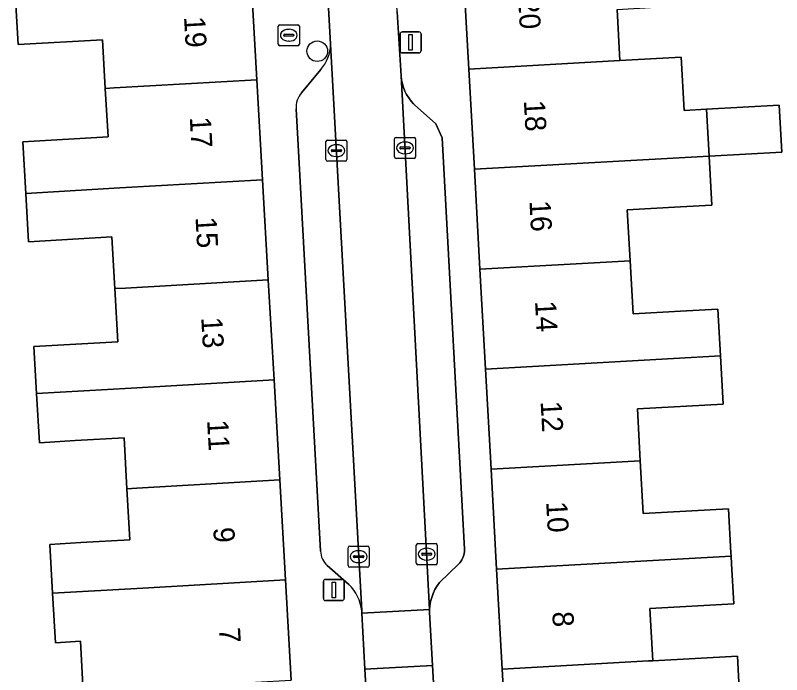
# Model space of a CAD drawing. Extents: x 160856 to 161310, y 384024 to 384878.
# Drawn here: x 161044.4 to 161080.75, y 384755.64 to 384786.93 of the extents above; entities that cross this region are included whole.
import ezdxf

# ---------------------------------------------------------------- set-up
doc = ezdxf.new("R2010")
doc.units = 0
for name, color, linetype in [('IMGEO_Boom', 7, 'Continuous'), ('IMGEO_Brandkraan', 7, 'Continuous'), ('IMGEO_Erf', 7, 'Continuous'), ('IMGEO_Kolk', 7, 'Continuous'), ('IMGEO_Lichtmast', 7, 'Continuous'), ('IMGEO_Pand', 7, 'Continuous'), ('IMGEO_Pand_nummerreeks', 7, 'Continuous'), ('IMGEO_Parkeervlak_open', 7, 'Continuous'), ('IMGEO_Rijbaan_lokaal_open', 7, 'Continuous'), ('IMGEO_Voetpad_open', 7, 'Continuous')]:
    doc.layers.add(name, color=color, linetype=linetype)

msp = doc.modelspace()

# ---------------------------------------------------------------- linework, layer by layer
at = {"layer": 'IMGEO_Boom'}
msp.add_circle((161058.723, 384785.224), 0.489, dxfattribs=at)
at = {"layer": 'IMGEO_Brandkraan'}
for p, q in [((161056.873, 384785.557), (161056.873, 384786.409)), ((161056.948, 384786.483), (161057.8, 384786.483)), ((161057.361, 384786.263), (161057.386, 384786.263)), ((161057.874, 384786.409), (161057.874, 384785.557)), ((161057.132, 384785.977), (161057.132, 384785.989)), ((161057.57, 384785.94), (161057.172, 384785.94)), ((161057.175, 384786.026), (161057.573, 384786.026)), ((161057.616, 384785.989), (161057.616, 384785.977)), ((161057.384, 384785.703), (161057.359, 384785.703)), ((161057.8, 384785.483), (161056.948, 384785.483))]:
    msp.add_line(p, q, dxfattribs=at)
for points in [[(161056.873, 384785.557), (161056.873, 384786.409)], [(161056.948, 384786.483), (161057.8, 384786.483)], [(161057.874, 384786.409), (161057.874, 384785.557)], [(161057.8, 384785.483), (161056.948, 384785.483)]]:
    msp.add_lwpolyline(points, dxfattribs=at)
for centre, radius, start, end in [((161056.95, 384786.407), 0.0765, 91.552, 178.448), ((161056.95, 384786.407), 0.0765, 91.552, 178.448), ((161057.798, 384786.407), 0.0765, 1.552, 88.448), ((161057.798, 384786.407), 0.0765, 1.552, 88.448), ((161057.172, 384785.986), 0.0403, 85.8775, 175.7526), ((161057.169, 384785.976), 0.0366, 178.938, 274.7102), ((161057.573, 384785.983), 0.043, 264.8664, 352.4533), ((161057.577, 384785.988), 0.0386, 1.7309, 96.639), ((161056.95, 384785.559), 0.0765, 181.552, 268.448), ((161056.95, 384785.559), 0.0765, 181.552, 268.448), ((161057.798, 384785.559), 0.0765, 271.552, 358.448), ((161057.798, 384785.559), 0.0765, 271.552, 358.448)]:
    msp.add_arc(centre, radius, start, end, dxfattribs=at)
for centre, major_axis, ratio, start_param, end_param in [((161057.36, 384785.983), (-0.387, 0.002), 0.722429, 4.712389, 7.853982), ((161057.385, 384785.983), (-0.39, 0.002), 0.717154, 1.570796, 4.712389)]:
    msp.add_ellipse(centre, major_axis=major_axis, ratio=ratio, start_param=start_param, end_param=end_param, dxfattribs=at)
at = {"layer": 'IMGEO_Erf'}
for points in [[(161047.627, 384754.817), (161047.489, 384757.224), (161046.302, 384757.156), (161046.168, 384759.498), (161046.035, 384761.818), (161047.517, 384761.903), (161049.834, 384762.036), (161049.695, 384764.464), (161049.558, 384766.875), (161047.24, 384766.743), (161045.541, 384766.646), (161045.408, 384768.982), (161045.281, 384771.204), (161049.263, 384771.434), (161049.117, 384773.958), (161049.102, 384774.223), (161048.976, 384776.411), (161045.027, 384776.185), (161044.896, 384778.48), (161044.756, 384780.929), (161048.801, 384781.161), (161048.67, 384783.459), (161048.538, 384785.766), (161044.542, 384785.537), (161044.402, 384787.978)], [(161072.949, 384787.211), (161073.083, 384784.777), (161075.991, 384784.939), (161076.132, 384782.412), (161077.185, 384782.47), (161080.631, 384782.66), (161080.753, 384780.441), (161077.309, 384780.251), (161077.438, 384777.926), (161075.957, 384777.843), (161073.43, 384777.701), (161073.566, 384775.283), (161073.707, 384772.761), (161076.232, 384772.901), (161077.732, 384772.984), (161077.856, 384770.761), (161077.983, 384768.478), (161073.91, 384768.252), (161074.047, 384765.789), (161074.186, 384763.289), (161078.225, 384763.513), (161078.345, 384761.413), (161078.353, 384761.267), (161078.374, 384760.898), (161078.482, 384758.995), (161074.501, 384758.773), (161074.639, 384756.3), (161078.652, 384756.524), (161078.791, 384754.027)]]:
    msp.add_lwpolyline(points, dxfattribs=at)
at = {"layer": 'IMGEO_Kolk'}
for p, q in [((161059.133, 384780.08), (161059.133, 384780.932)), ((161059.208, 384781.006), (161060.06, 384781.006)), ((161060.134, 384780.932), (161060.134, 384780.08)), ((161062.387, 384780.21), (161062.387, 384781.062)), ((161062.462, 384781.136), (161063.314, 384781.136)), ((161062.875, 384780.916), (161062.9, 384780.916)), ((161063.388, 384781.062), (161063.388, 384780.21)), ((161059.392, 384780.5), (161059.392, 384780.512)), ((161059.83, 384780.463), (161059.432, 384780.463)), ((161059.435, 384780.549), (161059.833, 384780.549)), ((161059.621, 384780.786), (161059.646, 384780.786)), ((161059.876, 384780.512), (161059.876, 384780.5)), ((161062.646, 384780.63), (161062.646, 384780.642)), ((161063.084, 384780.593), (161062.686, 384780.593)), ((161062.689, 384780.679), (161063.087, 384780.679)), ((161063.13, 384780.642), (161063.13, 384780.63)), ((161059.644, 384780.226), (161059.619, 384780.226)), ((161063.314, 384780.136), (161062.462, 384780.136)), ((161062.898, 384780.356), (161062.873, 384780.356)), ((161060.06, 384780.006), (161059.208, 384780.006)), ((161060.187, 384760.812), (161060.187, 384761.664)), ((161060.262, 384761.738), (161061.114, 384761.738)), ((161061.188, 384761.664), (161061.188, 384760.812)), ((161063.417, 384760.932), (161063.417, 384761.784)), ((161063.492, 384761.858), (161064.344, 384761.858)), ((161063.905, 384761.638), (161063.93, 384761.638)), ((161064.418, 384761.784), (161064.418, 384760.932)), ((161060.446, 384761.232), (161060.446, 384761.244)), ((161060.884, 384761.195), (161060.486, 384761.195)), ((161060.489, 384761.281), (161060.887, 384761.281)), ((161060.675, 384761.518), (161060.7, 384761.518)), ((161060.93, 384761.244), (161060.93, 384761.232)), ((161063.676, 384761.352), (161063.676, 384761.364)), ((161064.114, 384761.315), (161063.716, 384761.315)), ((161063.719, 384761.401), (161064.117, 384761.401)), ((161064.16, 384761.364), (161064.16, 384761.352)), ((161060.698, 384760.958), (161060.673, 384760.958)), ((161064.344, 384760.858), (161063.492, 384760.858)), ((161063.928, 384761.078), (161063.903, 384761.078)), ((161061.114, 384760.738), (161060.262, 384760.738))]:
    msp.add_line(p, q, dxfattribs=at)
for points in [[(161059.133, 384780.08), (161059.133, 384780.932)], [(161059.208, 384781.006), (161060.06, 384781.006)], [(161060.134, 384780.932), (161060.134, 384780.08)], [(161062.387, 384780.21), (161062.387, 384781.062)], [(161062.462, 384781.136), (161063.314, 384781.136)], [(161063.388, 384781.062), (161063.388, 384780.21)], [(161063.314, 384780.136), (161062.462, 384780.136)], [(161060.06, 384780.006), (161059.208, 384780.006)], [(161060.187, 384760.812), (161060.187, 384761.664)], [(161060.262, 384761.738), (161061.114, 384761.738)], [(161061.188, 384761.664), (161061.188, 384760.812)], [(161063.417, 384760.932), (161063.417, 384761.784)], [(161063.492, 384761.858), (161064.344, 384761.858)], [(161064.418, 384761.784), (161064.418, 384760.932)], [(161064.344, 384760.858), (161063.492, 384760.858)], [(161061.114, 384760.738), (161060.262, 384760.738)]]:
    msp.add_lwpolyline(points, dxfattribs=at)
for centre, radius, start, end in [((161059.21, 384780.93), 0.0765, 91.552, 178.448), ((161059.21, 384780.93), 0.0765, 91.552, 178.448), ((161060.058, 384780.93), 0.0765, 1.552, 88.448), ((161060.058, 384780.93), 0.0765, 1.552, 88.448), ((161062.464, 384781.06), 0.0765, 91.552, 178.448), ((161062.464, 384781.06), 0.0765, 91.552, 178.448), ((161063.312, 384781.06), 0.0765, 1.552, 88.448), ((161063.312, 384781.06), 0.0765, 1.552, 88.448), ((161059.432, 384780.509), 0.0403, 85.8775, 175.7526), ((161059.429, 384780.499), 0.0366, 178.938, 274.7102), ((161059.833, 384780.506), 0.043, 264.8664, 352.4533), ((161059.837, 384780.511), 0.0386, 1.7309, 96.639), ((161062.686, 384780.639), 0.0403, 85.8775, 175.7526), ((161062.683, 384780.629), 0.0366, 178.938, 274.7102), ((161063.087, 384780.636), 0.043, 264.8664, 352.4533), ((161063.091, 384780.641), 0.0386, 1.7309, 96.639), ((161059.21, 384780.082), 0.0765, 181.552, 268.448), ((161059.21, 384780.082), 0.0765, 181.552, 268.448), ((161060.058, 384780.082), 0.0765, 271.552, 358.448), ((161060.058, 384780.082), 0.0765, 271.552, 358.448), ((161062.464, 384780.212), 0.0765, 181.552, 268.448), ((161062.464, 384780.212), 0.0765, 181.552, 268.448), ((161063.312, 384780.212), 0.0765, 271.552, 358.448), ((161063.312, 384780.212), 0.0765, 271.552, 358.448), ((161060.264, 384761.662), 0.0765, 91.552, 178.448), ((161060.264, 384761.662), 0.0765, 91.552, 178.448), ((161061.112, 384761.662), 0.0765, 1.552, 88.448), ((161061.112, 384761.662), 0.0765, 1.552, 88.448), ((161063.494, 384761.782), 0.0765, 91.552, 178.448), ((161063.494, 384761.782), 0.0765, 91.552, 178.448), ((161064.342, 384761.782), 0.0765, 1.552, 88.448), ((161064.342, 384761.782), 0.0765, 1.552, 88.448), ((161060.486, 384761.241), 0.0403, 85.8775, 175.7526), ((161060.483, 384761.231), 0.0366, 178.938, 274.7102), ((161060.887, 384761.238), 0.043, 264.8664, 352.4533), ((161060.891, 384761.243), 0.0386, 1.7309, 96.639), ((161063.716, 384761.361), 0.0403, 85.8775, 175.7526), ((161063.713, 384761.351), 0.0366, 178.938, 274.7102), ((161064.117, 384761.358), 0.043, 264.8664, 352.4533), ((161064.121, 384761.363), 0.0386, 1.7309, 96.639), ((161060.264, 384760.814), 0.0765, 181.552, 268.448), ((161060.264, 384760.814), 0.0765, 181.552, 268.448), ((161061.112, 384760.814), 0.0765, 271.552, 358.448), ((161061.112, 384760.814), 0.0765, 271.552, 358.448), ((161063.494, 384760.934), 0.0765, 181.552, 268.448), ((161063.494, 384760.934), 0.0765, 181.552, 268.448), ((161064.342, 384760.934), 0.0765, 271.552, 358.448), ((161064.342, 384760.934), 0.0765, 271.552, 358.448)]:
    msp.add_arc(centre, radius, start, end, dxfattribs=at)
for centre, major_axis, ratio, start_param, end_param in [((161062.874, 384780.636), (-0.387, 0.002), 0.722429, 4.712389, 7.853982), ((161062.899, 384780.636), (-0.39, 0.002), 0.717154, 1.570796, 4.712389), ((161059.62, 384780.506), (-0.387, 0.002), 0.722429, 4.712389, 7.853982), ((161059.645, 384780.506), (-0.39, 0.002), 0.717154, 1.570796, 4.712389), ((161063.904, 384761.358), (-0.387, 0.002), 0.722429, 4.712389, 7.853982), ((161063.929, 384761.358), (-0.39, 0.002), 0.717154, 1.570796, 4.712389), ((161060.674, 384761.238), (-0.387, 0.002), 0.722429, 4.712389, 7.853982), ((161060.699, 384761.238), (-0.39, 0.002), 0.717154, 1.570796, 4.712389)]:
    msp.add_ellipse(centre, major_axis=major_axis, ratio=ratio, start_param=start_param, end_param=end_param, dxfattribs=at)
at = {"layer": 'IMGEO_Lichtmast'}
for p, q in [((161062.655, 384785.243), (161062.655, 384786.043)), ((161062.655, 384786.043), (161062.655, 384785.243)), ((161062.755, 384786.143), (161063.545, 384786.143)), ((161063.545, 384786.143), (161062.755, 384786.143)), ((161063.645, 384786.043), (161063.645, 384785.243)), ((161063.645, 384785.243), (161063.645, 384786.043)), ((161063.545, 384785.143), (161062.755, 384785.143)), ((161062.755, 384785.143), (161063.545, 384785.143)), ((161059.114, 384760.157), (161059.904, 384760.157)), ((161059.904, 384760.157), (161059.114, 384760.157)), ((161059.014, 384759.257), (161059.014, 384760.057)), ((161059.014, 384760.057), (161059.014, 384759.257)), ((161060.004, 384760.057), (161060.004, 384759.257)), ((161060.004, 384759.257), (161060.004, 384760.057)), ((161059.904, 384759.157), (161059.114, 384759.157)), ((161059.114, 384759.157), (161059.904, 384759.157))]:
    msp.add_line(p, q, dxfattribs=at)
for points in [[(161063.075, 384786.018), (161063.225, 384786.018), (161063.225, 384785.268), (161063.075, 384785.268), (161063.075, 384786.018)], [(161059.434, 384760.032), (161059.584, 384760.032), (161059.584, 384759.282), (161059.434, 384759.282), (161059.434, 384760.032)]]:
    msp.add_lwpolyline(points, dxfattribs=at)
for centre, start, end in [((161062.755, 384786.043), 90, 180), ((161062.755, 384786.043), 90, 180), ((161063.545, 384786.043), 0, 90), ((161063.545, 384786.043), 360, 90), ((161062.755, 384785.243), 180, 270), ((161062.755, 384785.243), 180, 270), ((161063.545, 384785.243), 270, 0), ((161063.545, 384785.243), 270, 0), ((161059.114, 384760.057), 90, 180), ((161059.114, 384760.057), 90, 180), ((161059.904, 384760.057), 0, 90), ((161059.904, 384760.057), 360, 90), ((161059.114, 384759.257), 180, 270), ((161059.114, 384759.257), 180, 270), ((161059.904, 384759.257), 270, 0), ((161059.904, 384759.257), 270, 0)]:
    msp.add_arc(centre, 0.1, start, end, dxfattribs=at)
at = {"layer": 'IMGEO_Pand'}
for points in [[(161076.944, 384787.431), (161076.815, 384789.745), (161072.586, 384789.51), (161065.65, 384789.125), (161065.914, 384784.379), (161073.083, 384784.777), (161072.949, 384787.211), (161075.856, 384787.371)], [(161055.585, 384788.618), (161048.811, 384788.23), (161044.402, 384787.978), (161044.542, 384785.537), (161048.538, 384785.766), (161048.67, 384783.459), (161049.083, 384783.483), (161055.857, 384783.87)], [(161075.991, 384784.939), (161073.083, 384784.777), (161065.914, 384784.379), (161066.178, 384779.633), (161077.309, 384780.251), (161077.185, 384782.47), (161076.132, 384782.412)], [(161055.857, 384783.87), (161049.083, 384783.483), (161048.67, 384783.459), (161048.801, 384781.161), (161044.756, 384780.929), (161044.896, 384778.48), (161049.355, 384778.735), (161056.129, 384779.122)], [(161077.185, 384782.47), (161077.309, 384780.251), (161080.753, 384780.441), (161080.631, 384782.66)], [(161075.957, 384777.843), (161077.438, 384777.926), (161077.309, 384780.251), (161066.178, 384779.633), (161066.442, 384774.887), (161073.566, 384775.283), (161073.43, 384777.701)], [(161056.129, 384779.122), (161049.355, 384778.735), (161044.896, 384778.48), (161045.027, 384776.185), (161048.976, 384776.411), (161049.102, 384774.223), (161049.117, 384773.958), (161049.627, 384773.987), (161056.4, 384774.374)], [(161073.566, 384775.283), (161066.442, 384774.887), (161066.705, 384770.141), (161077.856, 384770.761), (161077.732, 384772.984), (161076.232, 384772.901), (161073.707, 384772.761)], [(161056.4, 384774.374), (161049.627, 384773.987), (161049.117, 384773.958), (161049.263, 384771.434), (161045.281, 384771.204), (161045.408, 384768.982), (161049.899, 384769.239), (161056.672, 384769.627)], [(161066.705, 384770.141), (161066.969, 384765.395), (161074.047, 384765.789), (161073.91, 384768.252), (161077.983, 384768.478), (161077.856, 384770.761)], [(161056.672, 384769.627), (161049.899, 384769.239), (161045.408, 384768.982), (161045.541, 384766.646), (161047.24, 384766.743), (161049.558, 384766.875), (161049.695, 384764.464), (161050.171, 384764.491), (161056.944, 384764.879)], [(161074.186, 384763.289), (161074.047, 384765.789), (161066.969, 384765.395), (161067.233, 384760.649), (161078.353, 384761.267), (161078.345, 384761.413), (161078.225, 384763.513)], [(161056.944, 384764.879), (161050.171, 384764.491), (161049.695, 384764.464), (161049.834, 384762.036), (161047.517, 384761.903), (161046.035, 384761.818), (161046.168, 384759.498), (161050.443, 384759.743), (161057.215, 384760.131)], [(161074.501, 384758.773), (161078.482, 384758.995), (161078.374, 384760.898), (161078.353, 384761.267), (161067.233, 384760.649), (161067.497, 384755.903), (161074.434, 384756.289), (161074.639, 384756.3)], [(161057.215, 384760.131), (161050.443, 384759.743), (161046.168, 384759.498), (161046.302, 384757.156), (161047.489, 384757.224), (161047.627, 384754.817), (161050.212, 384754.966), (161050.715, 384754.995), (161057.487, 384755.383)], [(161078.652, 384756.524), (161074.639, 384756.3), (161074.434, 384756.289), (161067.497, 384755.903), (161067.761, 384751.157), (161074.698, 384751.543), (161078.91, 384751.777), (161078.896, 384752.04), (161078.881, 384752.303), (161078.8, 384753.863), (161078.791, 384754.027)]]:
    msp.add_lwpolyline(points, close=True, dxfattribs=at)
at = {"layer": 'IMGEO_Parkeervlak_open'}
for points in [[(161060.831, 384758.662), (161059.355, 384785.558)], [(161058.891, 384784.349), (161057.984, 384783.254)], [(161057.72, 384782.485), (161058.885, 384761.496)], [(161059.195, 384760.818), (161060.219, 384759.918)]]:
    msp.add_lwpolyline(points, dxfattribs=at)
msp.add_lwpolyline([(161062.707, 384784.049), (161064.049, 384758.727), (161064.065, 384758.911), (161064.1, 384759.109), (161064.153, 384759.303), (161064.222, 384759.492), (161064.308, 384759.673), (161064.41, 384759.847), (161064.527, 384760.01), (161065.428, 384760.886), (161065.484, 384760.946), (161065.535, 384761.011), (161065.58, 384761.08), (161065.618, 384761.153), (161065.649, 384761.229), (161065.674, 384761.307), (161065.692, 384761.388), (161065.702, 384761.469), (161065.705, 384761.551), (161065.704, 384761.592), (161064.644, 384781.111), (161064.342, 384781.773), (161063.339, 384782.68), (161063.296, 384782.723), (161063.172, 384782.861), (161063.061, 384783.009), (161062.964, 384783.167), (161062.881, 384783.333), (161062.814, 384783.505), (161062.762, 384783.683), (161062.726, 384783.865)], close=True, dxfattribs=at)
for centre, radius, start, end in [((161057.486, 384785.582), 1.87, 318.7415, 359.2661), ((161058.785, 384782.549), 1.067, 138.6546, 183.4504), ((161059.802, 384761.505), 0.917, 180.5798, 228.5626), ((161058.823, 384758.461), 2.018, 5.7244, 46.232)]:
    msp.add_arc(centre, radius, start, end, dxfattribs=at)
at = {"layer": 'IMGEO_Rijbaan_lokaal_open'}
for points in [[(161057.699, 384815.242), (161058.598, 384799.354), (161059.355, 384785.558), (161060.831, 384758.662), (161060.837, 384758.55), (161064.049, 384758.727), (161062.707, 384784.049), (161062.512, 384787.086), (161061.021, 384814.215), (161060.947, 384815.449)], [(161060.988, 384755.894), (161064.192, 384756.072), (161064.047, 384758.585), (161064.049, 384758.727), (161060.837, 384758.55)], [(161065.98, 384724.229), (161064.63, 384748.494), (161064.543, 384750), (161064.192, 384756.072), (161060.988, 384755.894), (161061.323, 384750), (161061.691, 384743.529), (161062.749, 384724.24), (161062.758, 384724.074)]]:
    msp.add_lwpolyline(points, close=True, dxfattribs=at)
at = {"layer": 'IMGEO_Voetpad_open'}
for points in [[(161067.761, 384751.157), (161067.497, 384755.903), (161067.233, 384760.649), (161066.969, 384765.395), (161066.705, 384770.141), (161066.442, 384774.887), (161066.178, 384779.633), (161065.914, 384784.379), (161065.65, 384789.125), (161065.386, 384793.871), (161065.123, 384798.617), (161064.859, 384803.362), (161064.595, 384808.108), (161064.331, 384812.854), (161064.068, 384817.6), (161063.797, 384822.467)], [(161053.677, 384821.973), (161053.956, 384817.105), (161054.227, 384812.357), (161054.499, 384807.609), (161054.77, 384802.862), (161055.039, 384798.114), (161055.314, 384793.366), (161055.585, 384788.618), (161055.857, 384783.87), (161056.129, 384779.122), (161056.4, 384774.374), (161056.672, 384769.627), (161056.944, 384764.879), (161057.215, 384760.131), (161057.487, 384755.383)], [(161059.355, 384785.558), (161058.598, 384799.354)], [(161062.512, 384787.086), (161062.707, 384784.049), (161062.726, 384783.865), (161062.762, 384783.683), (161062.814, 384783.505), (161062.881, 384783.333), (161062.964, 384783.167), (161063.061, 384783.009), (161063.172, 384782.861), (161063.296, 384782.723), (161063.339, 384782.68), (161064.342, 384781.773), (161064.644, 384781.111), (161065.704, 384761.592), (161065.705, 384761.551), (161065.702, 384761.469), (161065.692, 384761.388), (161065.674, 384761.307), (161065.649, 384761.229), (161065.618, 384761.153), (161065.58, 384761.08), (161065.535, 384761.011), (161065.484, 384760.946), (161065.428, 384760.886), (161064.527, 384760.01), (161064.41, 384759.847), (161064.308, 384759.673), (161064.222, 384759.492), (161064.153, 384759.303), (161064.1, 384759.109), (161064.065, 384758.911), (161064.049, 384758.727), (161064.047, 384758.585), (161064.192, 384756.072), (161064.543, 384750)], [(161057.984, 384783.254), (161058.891, 384784.349)], [(161058.885, 384761.496), (161057.72, 384782.485)], [(161060.219, 384759.918), (161059.195, 384760.818)], [(161060.529, 384741.299), (161061.583, 384742.73), (161061.691, 384743.529), (161061.323, 384750), (161060.988, 384755.894), (161060.837, 384758.55), (161060.831, 384758.662)]]:
    msp.add_lwpolyline(points, dxfattribs=at)
for centre, radius, start, end in [((161057.486, 384785.582), 1.87, 318.7415, 359.2661), ((161058.785, 384782.549), 1.067, 138.6546, 183.4504), ((161059.802, 384761.505), 0.917, 180.5798, 228.5626), ((161058.823, 384758.461), 2.018, 5.7244, 46.232)]:
    msp.add_arc(centre, radius, start, end, dxfattribs=at)

# ---------------------------------------------------------------- texts
at = {"layer": 'IMGEO_Pand_nummerreeks'}
for s, rotation, p in [('20', 273.1797, (161068.252, 384787.729)), ('19', 273.2747, (161052.402, 384786.85)), ('18', 273.1797, (161068.522, 384782.877)), ('17', 273.2747, (161052.674, 384782.095)), ('16', 273.1797, (161068.786, 384778.12)), ('15', 273.2771, (161052.946, 384777.339)), ('14', 273.1797, (161069.051, 384773.36)), ('13', 273.2771, (161053.218, 384772.583)), ('12', 273.1815, (161069.315, 384768.603)), ('11', 273.2771, (161053.496, 384767.714)), ('10', 273.1797, (161069.58, 384763.837)), ('9', 273.2771, (161053.788, 384762.612)), ('8', 273.1797, (161069.87, 384758.616)), ('7', 273.2771, (161054.06, 384757.856))]:
    msp.add_text(s, height=1, rotation=rotation, dxfattribs=at).set_placement(p)

doc.saveas('drawing.dxf')
